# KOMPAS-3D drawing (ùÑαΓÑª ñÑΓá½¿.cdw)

Views: Разрез
Referenced files: ×åðòåæ ÇóÁ.cdw
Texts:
  Задание Ш0
  Noncommercial version
  Фигурная скобка
  Номер узла
  Марка координационной оси
  VRCB
  Выносная надпись
  Обозначение узла
  Марка/позиционное обозначение с линией-выноской
  Марка/позиционное обозначение на линии
  Марка/позиционное обозначение без линии-выноски
  Заголовок таблицы отчета
  Ячейка таблицы отчета
  Symbol type A
  Ra 1,6
  Ra6,3
  Ra 3,2
  Js9
  Ra1,6
  Js9( 0,021)
  Verdana
  Ra 6.3
  Ra 3.2
  ДГТУ
Dimensions and other numbers on the sheet: 7; 207; 126; 75; 182; 4 îòâ; 34; 50; 60; 1õ45; 2 ôàñêè; 0,012; 0,02; 12; 0,03; 25; 53,8; 14; 1,25; 153; 20 46; 0; 8-Ñ; 204; 0.02; 0.08; 1:2; 1; 6.4; 2; 3; 4; 5; 6; 8; 9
